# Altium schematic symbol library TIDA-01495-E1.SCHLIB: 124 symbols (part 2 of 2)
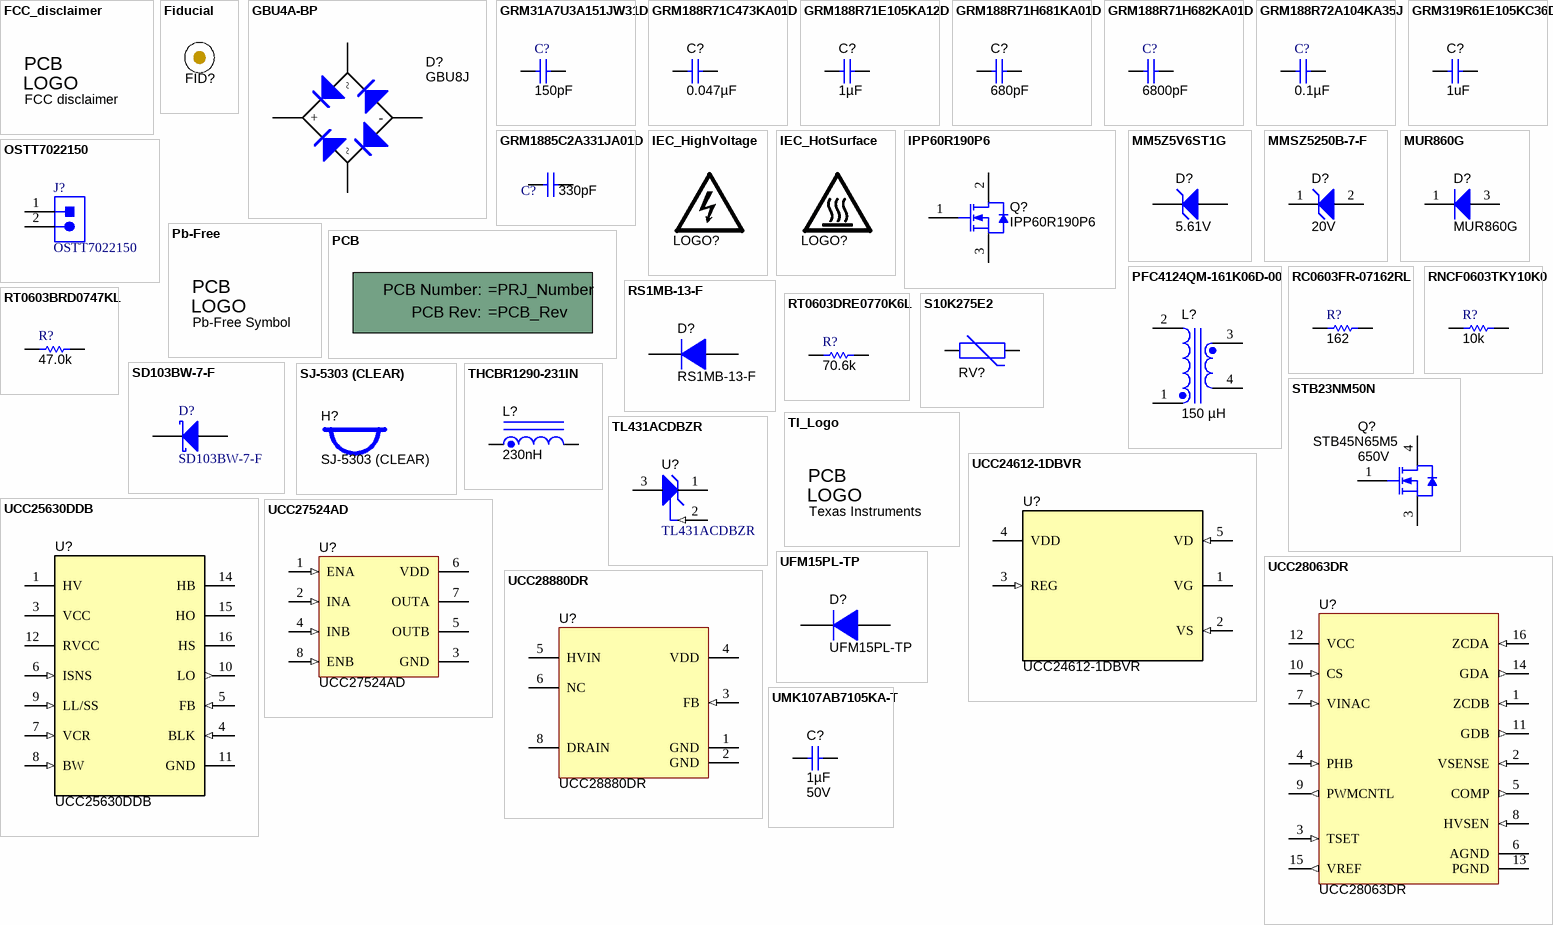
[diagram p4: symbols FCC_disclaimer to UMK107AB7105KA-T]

## UCC28063DR
designator U?
Natural Interleaving™ Transition-Mode PFC Controller with Improved Audible Noise Immunity, D0016A; Manufacturer: Texas Instruments; SymbolCreator: Altium; CompType: IC; U/M: EA
footprint D0016A_N
footprint D0016A_M
footprint D0016A_L
pins: 1 ZCDB (in), 2 VSENSE (in), 3 TSET (in), 4 PHB (in), 5 COMP (out), 6 AGND (power), 7 VINAC (in), 8 HVSEN (in), 9 PWMCNTL (out), 10 CS (in), 11 GDB (out), 12 VCC (power), 13 PGND (power), 14 GDA (out), 15 VREF (out), 16 ZCDA (in)

## UCC28880DR
designator U?
700-V Lowest Quiescent Current Off-Line Switcher, D0007A; Manufacturer: Texas Instruments; SymbolCreator: a0411947; CompType: IC; U/M: EA
footprint D0007A_N
footprint D0007A_M
footprint D0007A_L
pins: 1 GND (power) "Ground", 2 GND (power) "Ground", 3 FB (in) "Feedback terminal", 4 VDD (power) "Supply pin, supply is provided by internal LDO", 5 HVIN (power) "Supply pin", 6 NC "Not internally connected", 8 DRAIN (power) "Drain pin"
1 alternate drawing of the same symbol

## UFM15PL-TP
designator D?
Diode, Ultrafast, 600 V, 1 A, SOD-123FL; Manufacturer: Micro Commercial Components; U/M: EA; Vf_V: 1.7; Value: 600V; Value1: 1A; Value2: 1.7V; Io_A: 1; Vr_V: 600; TJmax_C: 150; SizeAreaWB_mm2: 12.19; SizeArea_mm2: 5.94; SizeX_mm: 3.6; SizeY_mm: 1.65; SizeZ_mm: 0.98; AEC Category: Q101; AEC Qualified: N; Green_Lifecycle: Not Set; Green_REACh: Incomplete
signal-integrity model Diode
footprint SOD-123FL
pins: 1 K, 2 A

## UMK107AB7105KA-T
designator C?  ValueDisplayed: 1µF  Value2: 50V  (hidden comment: UMK107AB7105KA-T)
CAP, CERM, 1 µF, 50 V, +/- 10%, X7R, 0603; Manufacturer: Taiyo Yuden; Polarized: N; CompType: Capacitor; Value: 1uF; U/M: EA; Cap_F: 0.000001; Tolerance_%: 10; Value1: Unknown; VDC_V: 50; TaMin_C: -55; TaMax_C: 125; Cap_Case: 0603
signal-integrity model Cap
simulation model Cap
footprint 0603
footprint 0603M
footprint 0603L
footprint 0603_HV
footprint 0603S
pins: 1, 2

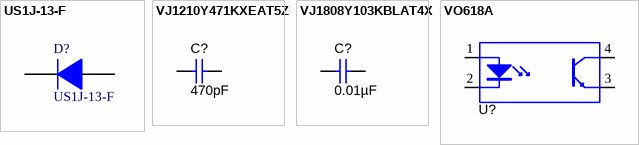
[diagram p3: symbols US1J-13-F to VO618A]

## US1J-13-F
designator D?
Diode, Ultrafast, 600 V, 1 A, SMA; Manufacturer: Diodes Inc.; U/M: EA; Vf_V: 1.7; Value: 600V; Value1: 1A; Value2: 1.7V; Io_A: 1; Vr_V: 600; TJmax_C: 150
signal-integrity model Diode
footprint SMA
pins: 1 K, 2 A

## VJ1210Y471KXEAT5Z
designator C?  ValueDisplayed: 470pF  (hidden comment: VJ1210Y471KXEAT5Z)
CAP, CERM, 470 pF, 500 V, +/- 10%, X7R, 1210; Manufacturer: Vishay-Vitramon; Polarized: N; CompType: Capacitor; Value: 470pF; U/M: EA; Cap_F: 0.00000000047; Tolerance_%: 10; Value1: Unknown; VDC_V: 500; Value2: 500V; TaMin_C: -55; TaMax_C: 125; Cap_Case: 1210; SizeArea_mm2: 8; SizeAreaWB_mm2: 14.7; SizeX_mm: 3.2; SizeY_mm: 2.5; SizeZ_mm: 1.35; AEC Category: Q200
signal-integrity model Cap
simulation model Cap
footprint 1210
footprint 1210M
footprint 1210L
pins: 1, 2

## VJ1808Y103KBLAT4X
designator C?  ValueDisplayed: 0.01µF  (hidden comment: VJ1808Y103KBLAT4X)
CAP, CERM, 0.01 µF, 630 V,+/- 10%, X7R, 1808; Manufacturer: Vishay-Vitramon; Polarized: N; CompType: Capacitor; Value: 0.01uF; U/M: EA; Cap_F: 0.00000001; Tolerance_%: 10; VDC_V: 630; Value2: 630V; TaMin_C: -55; TaMax_C: 125; Cap_Case: 1808; SizeArea_mm2: 9; SizeAreaWB_mm2: 16.5; SizeX_mm: 4.5; SizeY_mm: 2; SizeZ_mm: 2.03; AEC Category: Q200
signal-integrity model Cap
simulation model Cap
footprint 1808
footprint 1808_M
footprint 1808_L
pins: 1, 2

## VO618A
designator U?  (value not drawn)
Optocoupler, 5.3 kV, 50-600% CTR, TH; Manufacturer: Vishay-Semiconductor; CTR (Min): 50%; CTR (Max): 600%; Voltage_Isolation_Vrms: 5300V; SizeAreaWB_mm2: 71.064; SizeArea_mm2: 40.304; SizeX_mm: 8.8; SizeY_mm: 4.58; SizeZ_mm: 5
footprint DIP-4
pins: 1 A, 2 K, 3 E, 4 C
1 alternate drawing of the same symbol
